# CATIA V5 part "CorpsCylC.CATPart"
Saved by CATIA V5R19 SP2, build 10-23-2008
Part number: CorpsCylC
Publications: "Dc", "DbCylC", "HcylC", "DCylcExt", "EcorpscylC"
Bounding box of the stored display mesh (mm): x -50 to 50, y -49.993 to 50, z 0 to 310
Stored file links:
  C:\Users\Vianney\Documents\Garantie\Cours\2A\IAO\IAO-proj-Catia\CorpsCylC.CATPart
  C:\Users\Vianney\Documents\Garantie\Cours\2A\IAO\IAO-proj-Catia\CylindreC.CATPart
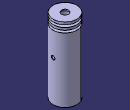
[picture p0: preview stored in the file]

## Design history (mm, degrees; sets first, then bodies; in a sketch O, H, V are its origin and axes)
Parameters
  EcorpscylC = 5 mm
  DbCylC = 30 mm
  Dc = 15 mm
  HcylC = 300 mm
  LENGTH = 0 mm
  DCylcExt = 100 mm
Body1 (main body)
  Sketch1 on yz-plane, origin (0, 0, 0), H (0, 1, 0), V (0, 0, 1)
    line L1 (0, 0) -> (50, 0)
    line L2 (50, 0) -> (50, 270)
    line L3 (50, 270) -> (25, 270)
    line L4 (25, 270) -> (25, 280)
    line L5 (25, 280) -> (50, 280)
    point P5 (50, 280)
    line L6 (50, 280) -> (50, 290)
    line L7 (50, 290) -> (25, 290)
    point P7 (25, 290)
    line L8 (25, 290) -> (25, 300)
    line L9 (25, 300) -> (50, 300)
    point P9 (50, 300)
    line L10 (50, 300) -> (50, 310)
    line L11 (0, 0) -> (0, 5)
    line L12 (0, 5) -> (45, 5)
    line L13 (45, 5) -> (45, 265)
    line L14 (45, 265) -> (20, 265)
    line L15 (20, 265) -> (20, 305)
    line L16 (50, 310) -> (15, 310)
    line L17 (15, 310) -> (15, 305)
    line L18 (15, 305) -> (20, 305)
    length L2 = 270 {= HcylC -30mm}
    length L1 = 50 {= DCylcExt  /2}
    distance L5 L1 = 280 {= HcylC -20mm}
    distance L7 L1 = 290 {= HcylC -10mm}
    distance L9 L1 = 300 {= HcylC}
    distance L15 L4 = 5 {= EcorpscylC}
    distance L17 V = 15 {= DbCylC /2}
    distance L1 L12 = 5 {= EcorpscylC}
    distance L13 L2 = 5 {= EcorpscylC}
    distance L14 L3 = 5 {= EcorpscylC}
    distance L18 L16 = 5 {= EcorpscylC}
    length L10 = 10
    distance L15 V = 20
    horizontal: L1 H, L3 H, L5 H, L7 H, L9 H, L12 H, L14 H, L16 H, L18 H
    vertical: L2 V, L4 V, L6 V, L8 V, L10 V, L11 V, L13 V, L15 V, L17 V
    coincidence: P5 L2, P7 L4, P9 L2
  Shaft1: profile Sketch1, axis Sketch1.V, angle 360
  Plane1: type Offset, RefPlane yz-plane, Offset 50 {= DCylcExt /2}
  Sketch2 on Plane1, origin (50, 0, 0), H (0, 1, 0), V (0, 0, 1)
    circle A1 centre (0, 170) radius 7.5
    point P1 (0, 170)
    radius A1 = 7.5 {= Dc /2}
    distance H P1 = 170 {= HcylC -130mm}
    coincidence: P1 V
  Pocket1: profile Sketch2, direction (-1, 0, 0), length 3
